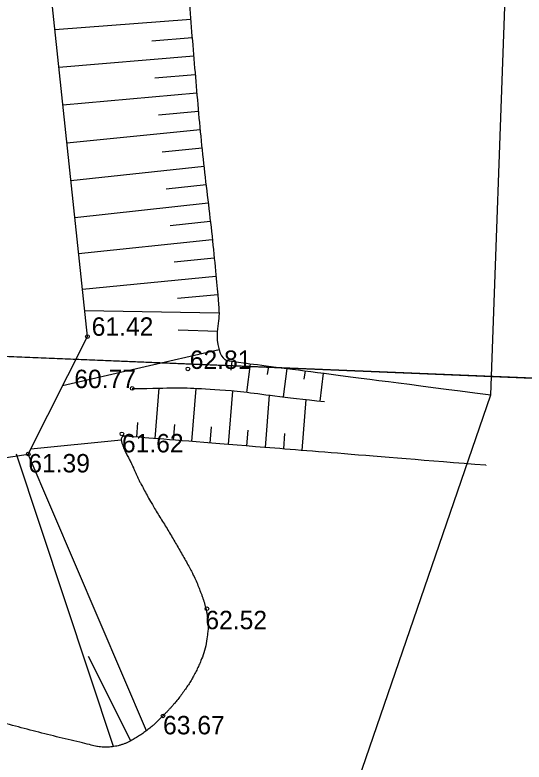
# Model space of a CAD drawing. Extents: x 616607 to 617499, y 408385 to 409695.
# Drawn here: x 617200.57 to 617214.38, y 409064.08 to 409084.35 of the extents above; entities that cross this region are included whole.
import ezdxf

# ---------------------------------------------------------------- set-up
doc = ezdxf.new("R2010")
doc.units = 0
for name, color, linetype in [('HIDG_GRAV_####_####_#', 7, 'Continuous'), ('RAMI_UZMR_####_####_#', 7, 'Continuous'), ('RELJ_AATZ_####_TKST_#', 7, 'Continuous'), ('RELJ_ELEM_####_####_#', 7, 'Continuous'), ('RELJ_NOGA_####_####_#', 7, 'Continuous'), ('RELJ_NOGL_####_####_#', 7, 'Continuous'), ('ROBZ_IERR_####_####_#', 7, 'Continuous'), ('ROBZ_UZMR_####_####_#', 7, 'Continuous')]:
    doc.layers.add(name, color=color, linetype=linetype)

# ---------------------------------------------------------------- blocks, each defined once
blk = doc.blocks.new('PKT')
at = {"layer": 'RELJ_ELEM_####_####_#'}
blk.add_circle((0, 0), 0.05, dxfattribs=at)

msp = doc.modelspace()

# ---------------------------------------------------------------- linework, layer by layer
at = {"layer": 'HIDG_GRAV_####_####_#'}
msp.add_lwpolyline([(617198.671, 409072.074), (617200.929, 409072.435), (617202.532, 409075.622), (617201.237, 409087.874), (617202.422, 409112.516), (617197.415, 409136.544), (617162.613, 409207.758), (617153.021, 409229.447), (617150.525, 409241.262), (617153.298, 409253.658), (617189.431, 409302.264), (617198.754, 409312.12), (617224.478, 409345.652), (617234.105, 409363.027), (617250.009, 409421.44), (617285.914, 409471.848), (617328.6, 409526.531)], dxfattribs=at)
at = {"layer": 'RAMI_UZMR_####_####_#'}
msp.add_lwpolyline([(617101.571, 408748.246), (617213.472, 409074.039), (617215.883, 409140.56), (617165.121, 409241.478), (617252.137, 409353.424), (617269.572, 409425.099), (617332.631, 409510.312), (617439.945, 409622.037), (617425.373, 409635.959), (617242.079, 409440.82), (617216.614, 409355.716), (617136.613, 409246.751), (617191.828, 409115.62), (617145.545, 408952.8)], dxfattribs=at)
at = {"layer": 'RELJ_NOGA_####_####_#'}
for p, q in [((617205.338, 409084.219), (617201.653, 409083.939)), ((617205.338, 409084.219), (617205.339, 409084.22)), ((617205.377, 409083.721), (617204.276, 409083.634)), ((617205.377, 409083.721), (617205.377, 409083.721)), ((617205.417, 409083.223), (617201.76, 409082.924)), ((617205.417, 409083.223), (617205.418, 409083.223)), ((617205.458, 409082.724), (617204.365, 409082.632)), ((617205.458, 409082.724), (617205.458, 409082.724)), ((617205.5, 409082.226), (617201.869, 409081.901)), ((617205.5, 409082.226), (617205.501, 409082.226)), ((617205.546, 409081.728), (617204.459, 409081.627)), ((617205.546, 409081.728), (617205.546, 409081.728)), ((617205.595, 409081.231), (617201.978, 409080.866)), ((617205.595, 409081.231), (617205.596, 409081.231)), ((617205.646, 409080.733), (617204.562, 409080.619)), ((617205.646, 409080.733), (617205.646, 409080.733)), ((617205.699, 409080.236), (617202.086, 409079.847)), ((617205.699, 409080.236), (617205.7, 409080.236)), ((617205.753, 409079.739), (617204.669, 409079.62)), ((617205.753, 409079.739), (617205.754, 409079.739)), ((617205.808, 409079.242), (617202.192, 409078.845)), ((617205.808, 409079.242), (617205.809, 409079.242)), ((617205.862, 409078.745), (617204.777, 409078.626)), ((617205.862, 409078.745), (617205.862, 409078.745)), ((617205.916, 409078.248), (617202.296, 409077.862)), ((617205.916, 409078.248), (617205.917, 409078.248)), ((617205.968, 409077.751), (617204.882, 409077.638)), ((617205.968, 409077.751), (617205.968, 409077.751)), ((617206.018, 409077.253), (617202.397, 409076.897)), ((617206.018, 409077.253), (617206.019, 409077.253)), ((617206.066, 409076.755), (617204.98, 409076.656)), ((617206.066, 409076.755), (617206.066, 409076.755)), ((617206.096, 409076.257), (617202.459, 409076.317)), ((617206.096, 409076.257), (617206.097, 409076.257)), ((617206.067, 409075.757), (617204.998, 409075.796)), ((617206.067, 409075.757), (617206.067, 409075.757)), ((617206.103, 409075.261), (617201.859, 409074.283)), ((617206.103, 409075.26), (617206.102, 409075.26)), ((617206.103, 409075.261), (617206.104, 409075.261)), ((617206.452, 409074.95), (617206.421, 409074.711)), ((617206.948, 409074.885), (617206.846, 409074.103)), ((617207.444, 409074.821), (617207.413, 409074.589)), ((617207.939, 409074.757), (617207.84, 409073.987)), ((617208.435, 409074.692), (617208.406, 409074.463)), ((617208.931, 409074.628), (617208.833, 409073.872)), ((617209.427, 409074.564), (617209.427, 409074.563)), ((617209.923, 409074.499), (617209.923, 409074.498)), ((617210.419, 409074.435), (617210.419, 409074.435)), ((617204.369, 409072.854), (617204.48, 409074.222)), ((617205.366, 409072.774), (617205.483, 409074.215)), ((617210.915, 409074.371), (617210.914, 409074.37)), ((617211.41, 409074.306), (617211.41, 409074.306)), ((617211.906, 409074.242), (617211.906, 409074.241)), ((617212.402, 409074.177), (617212.402, 409074.177)), ((617206.363, 409072.693), (617206.48, 409074.14)), ((617207.36, 409072.612), (617207.474, 409074.031)), ((617212.898, 409074.113), (617212.898, 409074.112)), ((617213.394, 409074.049), (617213.394, 409074.049)), ((617208.356, 409072.532), (617208.468, 409073.912)), ((617203.871, 409072.895), (617203.903, 409073.29)), ((617204.868, 409072.814), (617204.902, 409073.238)), ((617205.865, 409072.733), (617205.9, 409073.168)), ((617206.861, 409072.653), (617206.896, 409073.083)), ((617207.858, 409072.572), (617207.892, 409072.992)), ((617203.453, 409072.807), (617200.996, 409072.569)), ((617203.453, 409072.807), (617203.454, 409072.807)), ((617203.871, 409072.895), (617203.871, 409072.894)), ((617204.369, 409072.854), (617204.369, 409072.853)), ((617204.868, 409072.814), (617204.868, 409072.814)), ((617205.366, 409072.774), (617205.366, 409072.773)), ((617205.865, 409072.733), (617205.865, 409072.733)), ((617206.363, 409072.693), (617206.363, 409072.692)), ((617206.861, 409072.653), (617206.861, 409072.652)), ((617207.36, 409072.612), (617207.36, 409072.611)), ((617207.858, 409072.572), (617207.858, 409072.572)), ((617203.243, 409064.499), (617200.608, 409072.431)), ((617204.135, 409064.927), (617200.929, 409072.435)), ((617208.356, 409072.532), (617208.356, 409072.531)), ((617208.855, 409072.491), (617208.855, 409072.492)), ((617208.855, 409072.491), (617208.855, 409072.491)), ((617209.353, 409072.451), (617209.353, 409072.452)), ((617209.353, 409072.451), (617209.353, 409072.45)), ((617209.852, 409072.411), (617209.852, 409072.41)), ((617209.852, 409072.411), (617209.852, 409072.411)), ((617210.35, 409072.37), (617210.35, 409072.371)), ((617210.35, 409072.37), (617210.35, 409072.369)), ((617203.639, 409072.345), (617203.64, 409072.345)), ((617203.639, 409072.345), (617203.639, 409072.345)), ((617210.848, 409072.33), (617210.848, 409072.33)), ((617210.848, 409072.33), (617210.848, 409072.33)), ((617211.347, 409072.29), (617211.347, 409072.291)), ((617211.347, 409072.29), (617211.347, 409072.289)), ((617211.845, 409072.249), (617211.845, 409072.25)), ((617211.845, 409072.249), (617211.845, 409072.249)), ((617212.343, 409072.209), (617212.343, 409072.21)), ((617212.343, 409072.209), (617212.343, 409072.208)), ((617212.842, 409072.169), (617212.842, 409072.168)), ((617212.842, 409072.169), (617212.842, 409072.169)), ((617213.34, 409072.128), (617213.34, 409072.129)), ((617213.34, 409072.128), (617213.34, 409072.127)), ((617203.854, 409071.894), (617203.853, 409071.893)), ((617203.854, 409071.894), (617203.855, 409071.894)), ((617204.079, 409071.447), (617204.078, 409071.447)), ((617204.079, 409071.447), (617204.079, 409071.447)), ((617204.325, 409071.012), (617204.324, 409071.012)), ((617204.325, 409071.012), (617204.326, 409071.013)), ((617204.583, 409070.584), (617204.584, 409070.584)), ((617204.583, 409070.584), (617204.583, 409070.584)), ((617204.843, 409070.157), (617204.844, 409070.158)), ((617204.843, 409070.157), (617204.843, 409070.157)), ((617205.098, 409069.727), (617205.097, 409069.726)), ((617205.098, 409069.727), (617205.098, 409069.727)), ((617205.336, 409069.287), (617205.335, 409069.287)), ((617205.336, 409069.287), (617205.337, 409069.287)), ((617205.546, 409068.834), (617205.547, 409068.834)), ((617205.546, 409068.834), (617205.546, 409068.834)), ((617205.713, 409068.363), (617205.712, 409068.362)), ((617205.713, 409068.363), (617205.714, 409068.363)), ((617205.799, 409067.871), (617205.8, 409067.871)), ((617205.799, 409067.871), (617205.799, 409067.871)), ((617205.767, 409067.373), (617205.766, 409067.374)), ((617205.767, 409067.373), (617205.768, 409067.373)), ((617203.715, 409064.657), (617202.562, 409066.94)), ((617205.635, 409066.892), (617205.636, 409066.892)), ((617205.635, 409066.892), (617205.635, 409066.892)), ((617205.427, 409066.438), (617205.426, 409066.439)), ((617205.427, 409066.438), (617205.427, 409066.438)), ((617205.161, 409066.015), (617205.16, 409066.015)), ((617205.161, 409066.015), (617205.161, 409066.015)), ((617204.852, 409065.622), (617204.851, 409065.623)), ((617204.852, 409065.622), (617204.853, 409065.621)), ((617204.51, 409065.257), (617204.51, 409065.258)), ((617204.51, 409065.257), (617204.51, 409065.257)), ((617200.804, 409064.994), (617200.804, 409064.994)), ((617201.289, 409064.871), (617201.289, 409064.87)), ((617204.135, 409064.927), (617204.136, 409064.926)), ((617201.774, 409064.749), (617201.774, 409064.749)), ((617203.715, 409064.657), (617203.715, 409064.657)), ((617202.259, 409064.63), (617202.259, 409064.629)), ((617202.746, 409064.514), (617202.746, 409064.514)), ((617203.243, 409064.499), (617203.243, 409064.498))]:
    msp.add_line(p, q, dxfattribs=at)
for points in [[(617336.806, 409523.735), (617334.087, 409521.174), (617331.368, 409518.613), (617328.65, 409516.053), (617321.193, 409509.03), (617314.57, 409501.094), (617308.568, 409492.793), (617305.546, 409488.614), (617302.537, 409484.426), (617299.516, 409480.247), (617296.49, 409476.063), (617293.469, 409471.875), (617290.436, 409467.695), (617287.772, 409464.025), (617284.965, 409460.461), (617282.252, 409456.826), (617279.55, 409453.205), (617276.887, 409449.558), (617274.256, 409445.882), (617271.624, 409442.206), (617269.17, 409438.414), (617266.782, 409434.573), (617265.581, 409432.642), (617264.455, 409430.674), (617263.346, 409428.69), (617262.228, 409426.69), (617261.169, 409424.668), (617260.166, 409422.606), (617258.56, 409419.302), (617257.132, 409415.931), (617255.903, 409412.47), (617254.682, 409409.035), (617253.531, 409405.585), (617252.579, 409402.073), (617251.627, 409398.563), (617250.683, 409395.052), (617249.746, 409391.538), (617248.81, 409388.023), (617247.876, 409384.508), (617246.956, 409380.989), (617246.456, 409379.078), (617246.028, 409377.149), (617245.649, 409375.21), (617245.269, 409373.268), (617244.984, 409371.31), (617244.622, 409369.366), (617244.259, 409367.42), (617243.878, 409365.48), (617243.456, 409363.545), (617243.245, 409362.576), (617242.967, 409361.625), (617242.691, 409360.672), (617242.413, 409359.713), (617242.093, 409358.772), (617241.734, 409357.838), (617241.092, 409356.173), (617240.315, 409354.578), (617239.389, 409353.048), (617238.465, 409351.519), (617237.498, 409350.034), (617236.402, 409348.636), (617235.3, 409347.23), (617234.195, 409345.828), (617233.083, 409344.431), (617231.973, 409343.038), (617230.863, 409341.647), (617229.743, 409340.262), (617227.764, 409337.815), (617225.693, 409335.438), (617223.461, 409333.217), (617221.215, 409330.983), (617218.873, 409328.856), (617216.607, 409326.646), (617214.346, 409324.442), (617212.093, 409322.231), (617209.875, 409319.98), (617208.771, 409318.86), (617207.791, 409317.635), (617206.772, 409316.432), (617205.753, 409315.229), (617204.825, 409314.017), (617203.96, 409312.646), (617203.768, 409312.342), (617203.633, 409312.004), (617203.62, 409311.655), (617203.607, 409311.284), (617203.603, 409310.913), (617203.599, 409310.542), (617203.595, 409310.167), (617203.603, 409309.793), (617203.596, 409309.419), (617203.588, 409309.066), (617203.48, 409308.714), (617203.309, 409308.4), (617202.615, 409307.13), (617201.9, 409305.914), (617201.16, 409304.689), (617200.419, 409303.462), (617199.689, 409302.232), (617198.921, 409301.021), (617197.385, 409298.6), (617195.744, 409296.251), (617194.012, 409293.966), (617188.331, 409286.47), (617182.548, 409279.072), (617176.617, 409271.78), (617175.091, 409269.904), (617173.565, 409268.03), (617172.006, 409266.181), (617170.46, 409264.348), (617168.875, 409262.548), (617167.326, 409260.717), (617165.749, 409258.854), (617164.19, 409256.978), (617162.652, 409255.082), (617161.86, 409254.106), (617161.109, 409253.1), (617160.341, 409252.105), (617159.552, 409251.081), (617158.796, 409250.055), (617158.061, 409248.97), (617157.091, 409247.54), (617156.549, 409245.874), (617156.301, 409244.175), (617156.178, 409243.327), (617156.153, 409242.478), (617156.175, 409241.631), (617156.198, 409240.798), (617156.24, 409239.966), (617156.347, 409239.134), (617156.709, 409236.311), (617157.141, 409233.481), (617158.294, 409230.866), (617161.329, 409223.986), (617164.552, 409217.339), (617167.894, 409210.677), (617170.758, 409204.966), (617173.578, 409199.236), (617176.506, 409193.56), (617179.423, 409187.907), (617182.384, 409182.277), (617185.301, 409176.624), (617188.243, 409170.922), (617191.171, 409165.213), (617194.071, 409159.489), (617195.541, 409156.585), (617196.952, 409153.652), (617198.382, 409150.727), (617199.832, 409147.761), (617201.227, 409144.774), (617202.61, 409141.772), (617203.681, 409139.449), (617204.533, 409137.047), (617205.282, 409134.589), (617206.022, 409132.164), (617206.554, 409129.71), (617206.943, 409127.212), (617207.329, 409124.726), (617207.611, 409122.242), (617207.809, 409119.738), (617208.005, 409117.248), (617208.126, 409114.753), (617208.097, 409112.263), (617208.074, 409110.266), (617207.983, 409108.256), (617207.635, 409106.282), (617207.283, 409104.281), (617206.913, 409102.294), (617206.558, 409100.3), (617206.203, 409098.306), (617205.85, 409096.331), (617205.506, 409094.315), (617205.165, 409092.324), (617205.06, 409090.322), (617205.116, 409088.325), (617205.171, 409086.355), (617205.316, 409084.384), (617205.484, 409082.414), (617205.653, 409080.435), (617205.914, 409078.469), (617206.09, 409076.495), (617206.126, 409076.085), (617206.005, 409075.66), (617206.103, 409075.26)], [(617206.103, 409075.26), (617206.137, 409075.123), (617206.26, 409074.975), (617206.4, 409074.956), (617208.757, 409074.65), (617211.115, 409074.345), (617213.472, 409074.039)], [(617203.465, 409072.886), (617203.454, 409072.868), (617203.452, 409072.844), (617203.452, 409072.823), (617203.453, 409072.794), (617203.458, 409072.764), (617203.467, 409072.735), (617203.494, 409072.657), (617203.521, 409072.584), (617203.556, 409072.512), (617203.614, 409072.395), (617203.677, 409072.281), (617203.733, 409072.163), (617203.747, 409072.133), (617203.762, 409072.102), (617203.776, 409072.071), (617203.812, 409071.992), (617203.846, 409071.912), (617203.883, 409071.833), (617203.919, 409071.753), (617203.959, 409071.674), (617204, 409071.595), (617204.084, 409071.435), (617204.171, 409071.277), (617204.262, 409071.121), (617204.447, 409070.802), (617204.646, 409070.491), (617204.833, 409070.174), (617205.018, 409069.862), (617205.197, 409069.547), (617205.367, 409069.226), (617205.448, 409069.072), (617205.516, 409068.913), (617205.58, 409068.751), (617205.612, 409068.672), (617205.64, 409068.593), (617205.667, 409068.513), (617205.694, 409068.434), (617205.717, 409068.355), (617205.738, 409068.274), (617205.768, 409068.156), (617205.784, 409068.036), (617205.797, 409067.916), (617205.809, 409067.795), (617205.808, 409067.671), (617205.792, 409067.55), (617205.757, 409067.295), (617205.7, 409067.044), (617205.601, 409066.805), (617205.574, 409066.737), (617205.545, 409066.672), (617205.513, 409066.608), (617205.481, 409066.544), (617205.45, 409066.48), (617205.416, 409066.418), (617205.348, 409066.294), (617205.272, 409066.174), (617205.191, 409066.058), (617205.102, 409065.932), (617205.01, 409065.809), (617204.91, 409065.691), (617204.859, 409065.63), (617204.807, 409065.569), (617204.753, 409065.51), (617204.697, 409065.449), (617204.641, 409065.39), (617204.584, 409065.331), (617204.511, 409065.257), (617204.436, 409065.186), (617204.36, 409065.116), (617204.309, 409065.069), (617204.256, 409065.024), (617204.202, 409064.981), (617204.148, 409064.937), (617204.093, 409064.896), (617204.037, 409064.857), (617203.98, 409064.817), (617203.921, 409064.78), (617203.862, 409064.744), (617203.802, 409064.706), (617203.741, 409064.672), (617203.678, 409064.639), (617203.604, 409064.601), (617203.528, 409064.572), (617203.449, 409064.546), (617203.371, 409064.521), (617203.291, 409064.505), (617203.21, 409064.494), (617203.131, 409064.484), (617203.051, 409064.478), (617202.971, 409064.484), (617202.89, 409064.489), (617202.808, 409064.499), (617202.728, 409064.518), (617202.089, 409064.671), (617201.454, 409064.824), (617200.82, 409064.99), (617200.184, 409065.156), (617199.547, 409065.321), (617198.911, 409065.489), (617198.275, 409065.656), (617197.639, 409065.826), (617197.002, 409065.993), (617196.464, 409066.134), (617195.924, 409066.274), (617195.384, 409066.409)], [(617213.34, 409072.128), (617210.079, 409072.392), (617206.818, 409072.656), (617203.556, 409072.92), (617203.524, 409072.923), (617203.482, 409072.914), (617203.465, 409072.886)]]:
    msp.add_open_spline(points, degree=3, dxfattribs=at)
at = {"layer": 'RELJ_NOGL_####_####_#'}
msp.add_open_spline([(617203.748, 409074.213), (617204.342, 409074.213), (617204.938, 409074.243), (617205.531, 409074.213), (617206.678, 409074.154), (617207.819, 409073.976), (617208.963, 409073.858)], degree=3, dxfattribs=at)
at = {"layer": 'ROBZ_IERR_####_####_#'}
msp.add_lwpolyline([(617119.605, 409263.967), (617148.652, 409247.272), (617150.138, 409230.13), (617196.507, 409136.07), (617200.886, 409119.423), (617196.025, 409075.262), (617232.282, 409073.757)], dxfattribs=at)
at = {"layer": 'ROBZ_UZMR_####_####_#'}
msp.add_lwpolyline([(617232.583, 409073.745), (617196.025, 409075.262), (617200.886, 409119.423), (617196.507, 409136.07), (617150.138, 409230.13), (617148.652, 409247.272), (617201.229, 409318.934), (617233.453, 409357.938), (617244.928, 409391.934), (617250.98, 409414.497), (617255.789, 409432.426), (617326.39, 409521.291), (617332.188, 409529.592), (617332.358, 409529.835), (617335.391, 409534.333), (617341.051, 409533.641), (617349.913, 409536.856), (617370.73, 409556.7), (617378.749, 409547.935), (617381.343, 409545.1)], dxfattribs=at)

# ---------------------------------------------------------------- block references
at = {"layer": 'RELJ_ELEM_####_####_#'}
for p in [(617202.532, 409075.622), (617205.259, 409074.742), (617203.748, 409074.213), (617203.469, 409072.979), (617200.929, 409072.435), (617205.773, 409068.239), (617204.584, 409065.331)]:
    msp.add_blockref('PKT', p, dxfattribs=at)

# ---------------------------------------------------------------- texts
at = {"layer": 'RELJ_AATZ_####_TKST_#'}
for s, p in [('61.42', (617202.649, 409075.642)), ('62.81', (617205.309, 409074.743)), ('60.77', (617202.178, 409074.222)), ('61.62', (617203.469, 409072.479)), ('61.39', (617200.929, 409071.935)), ('62.52', (617205.732, 409067.682)), ('63.67', (617204.584, 409064.831))]:
    msp.add_text(s, height=0.5, dxfattribs=at).set_placement(p)

doc.saveas('drawing.dxf')
